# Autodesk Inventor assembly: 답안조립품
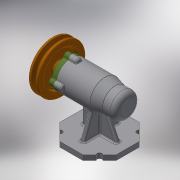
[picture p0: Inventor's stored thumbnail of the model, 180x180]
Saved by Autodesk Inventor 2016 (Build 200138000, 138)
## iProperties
Created: 2019-12
Part Number: 답안조립품
Material: 일반
Document SubType Name: Assembly
Designer: woori
Author: woori
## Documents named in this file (12)
- C:\Users\woori\Desktop\491204V1035\답안조립품.iam
- C:\Users\woori\Desktop\491204V1035\본체.ipt
- C:\Users\woori\Desktop\491204V1035\V벨트풀리.ipt
- C:\Users\woori\Desktop\491204V1035\멈춤나사 M3.ipt
- C:\Users\woori\Desktop\491204V1035\베어링 6004.ipt
- C:\Users\woori\Desktop\491204V1035\베어링 51202.ipt
- C:\Users\woori\Desktop\491204V1035\볼트 M4.ipt
- C:\Users\woori\Desktop\491204V1035\어댑터슬리브.ipt
- C:\Users\woori\Desktop\491204V1035\오일 실.ipt
- C:\Users\woori\Desktop\491204V1035\축.ipt
- C:\Users\woori\Desktop\491204V1035\커버.ipt
- C:\Users\woori\Desktop\491204V1035\키 5 x 5 x 16.ipt
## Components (1 placed, 1 different names)
1. V벨트풀리:1 — 각도:2
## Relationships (1: Angle 1)
- 각도:2 [Angle]: V벨트풀리:1
